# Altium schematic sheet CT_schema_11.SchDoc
size 386 x 278 mm
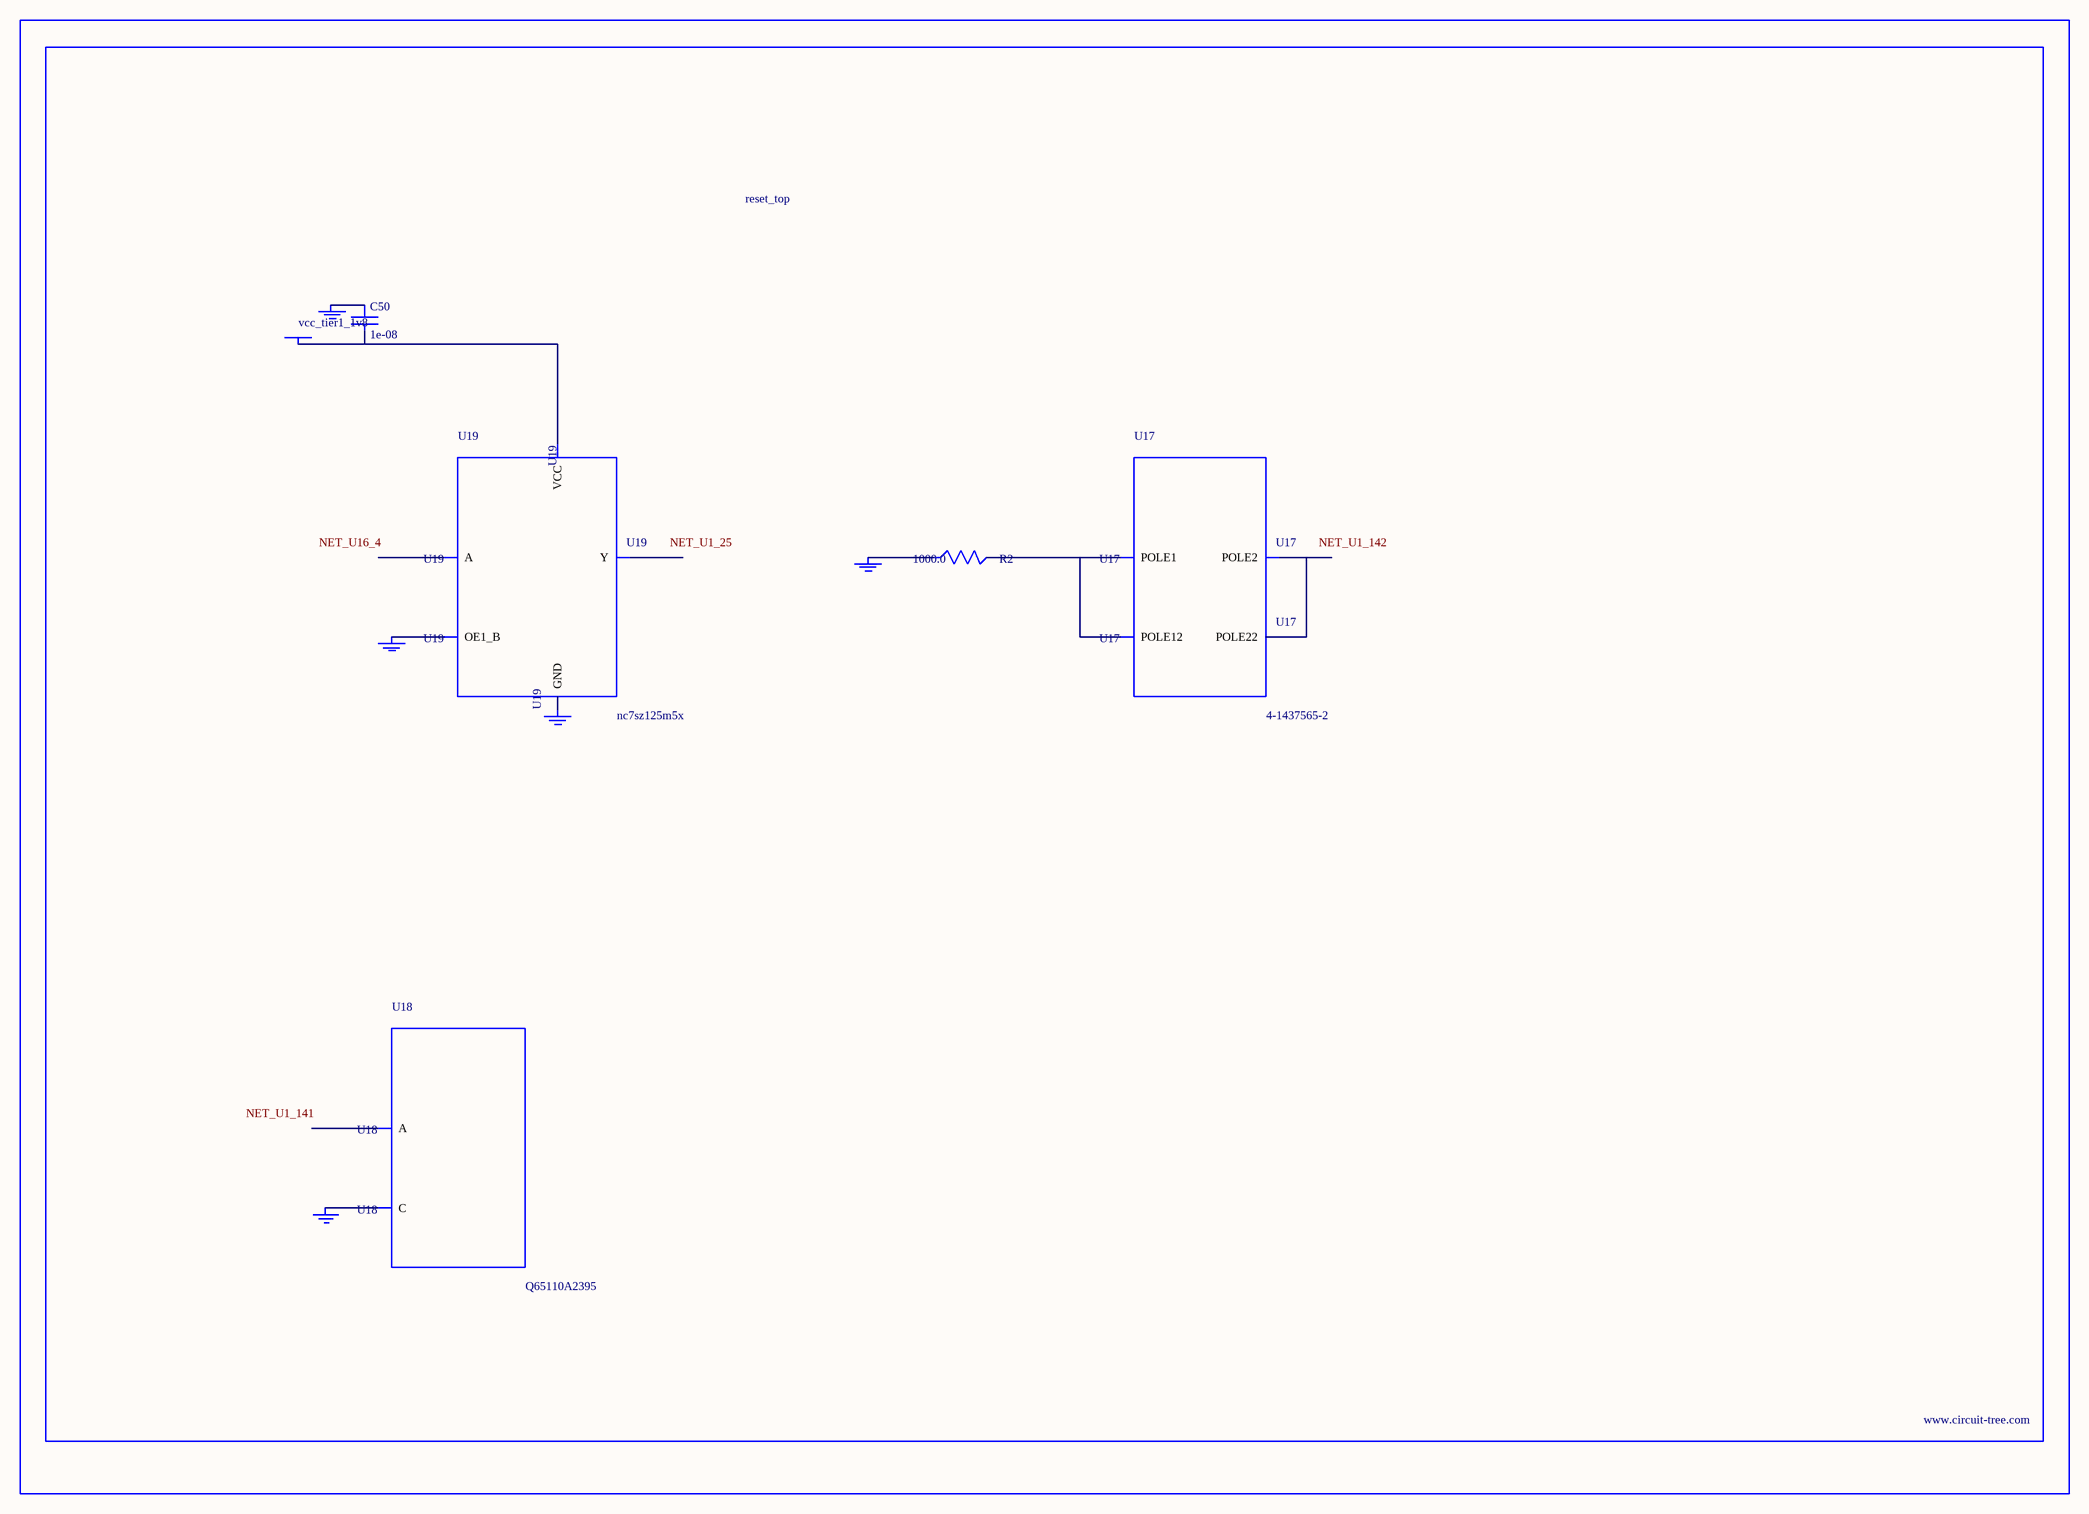
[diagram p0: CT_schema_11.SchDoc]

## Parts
BORDER10  (no value)
C50  1e-08  [C0402]
GND_INSTANCE_10_0  (no value)
GND_INSTANCE_10_1  (no value)
GND_INSTANCE_10_2  (no value)
GND_INSTANCE_10_3  (no value)
GND_INSTANCE_10_4  (no value)
POWER_INSTANCE_10_0  vcc_tier1_1v8
R2  1000.0  [R0603]
U17  4-1437565-2  [SW_4-1437565-2]
U18  Q65110A2395  [LGM67K-G1J2-24-Z]
U19  nc7sz125m5x  [NC7SZ125M5X]

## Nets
NetC50_1: C50.1 GND_INSTANCE_10_2.0(GND)
NetC50_2: C50.2 POWER_INSTANCE_10_0.0(PWR) U19.5(VCC)
NetGND_INSTANCE_10_0_0: GND_INSTANCE_10_0.0(GND) R2.1
NetGND_INSTANCE_10_1_0: GND_INSTANCE_10_1.0(GND) U18.C
NetGND_INSTANCE_10_3_0: GND_INSTANCE_10_3.0(GND) U19.1(OE1_B)
NetGND_INSTANCE_10_4_0: GND_INSTANCE_10_4.0(GND) U19.3(GND)
NetR2_2: R2.2 U17.1(POLE1) U17.2(POLE12)
NetU17_3: U17.3(POLE2) U17.4(POLE22)

Not connected (* = marked no-connect by the designer): U18 A; U19 2(A) 4(Y)

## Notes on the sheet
- Labels drawn without touching a wire or pin: NET_U1_25, NET_U1_141, NET_U1_142, NET_U16_4

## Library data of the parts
BORDER10 = BORDER_PAGE10
C50 = C0402C103K3RAC
GND_INSTANCE_10_0-GND_INSTANCE_10_4 = GND
POWER_INSTANCE_10_0 = PWR
R2 = RC0603JR-071KL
